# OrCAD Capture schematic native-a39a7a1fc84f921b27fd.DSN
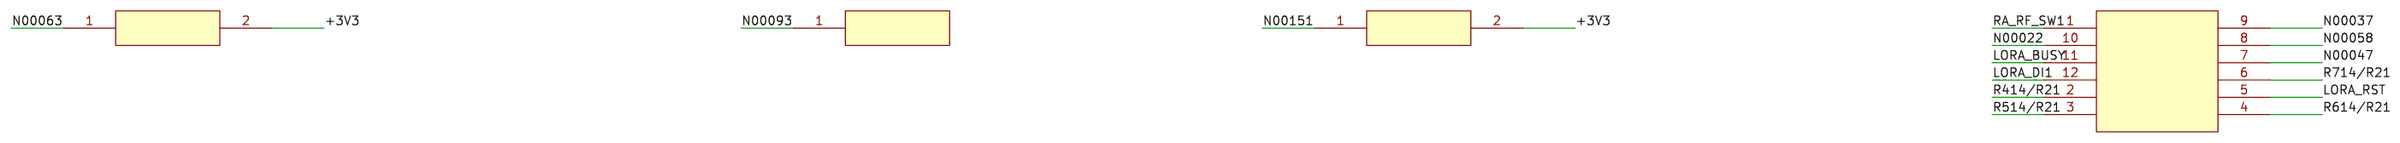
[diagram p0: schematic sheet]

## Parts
R1  10K
R2  330R
R3  10K
U1  Wio-SX1262

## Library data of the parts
R1 = OBS_R1
R2 = OBS_R2
R3 = OBS_R3
U1 = OBS_U1

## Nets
+3V3: R1.2 R3.2
LORA_BUSY: U1.11
LORA_DI1: U1.12
LORA_RST: U1.5
R414/R21: U1.2
R514/R21: U1.3
R614/R21: U1.4
R714/R21: U1.6
RA_RF_SW1: U1.1

Not connected (* = marked no-connect by the designer): R1 1; R2 1; R3 1; U1 7 8 9 10
